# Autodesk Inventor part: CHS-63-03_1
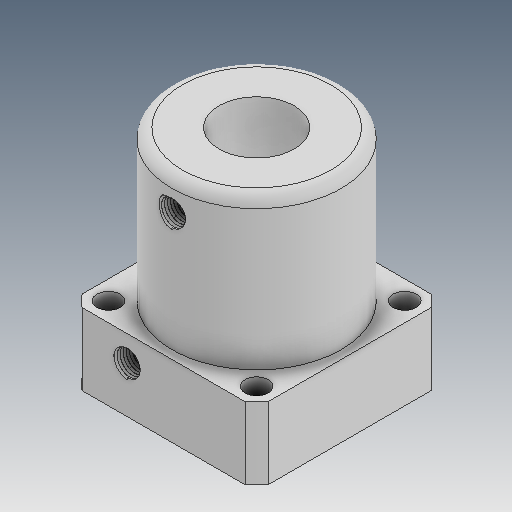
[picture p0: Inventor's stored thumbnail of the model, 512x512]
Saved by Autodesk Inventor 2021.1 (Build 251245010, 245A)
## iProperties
Created: 2019-05
Part Number: CHS-63-03_1
Material: Ogólny
Document SubType Name: Modeling
Designer: user
Density: 1 g/cm^3
Appearance: Domyślna
Author: user
Revision Number: ÈÎºÎ
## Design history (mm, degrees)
feature "ÊäÈë1"
node "Bryła1"
